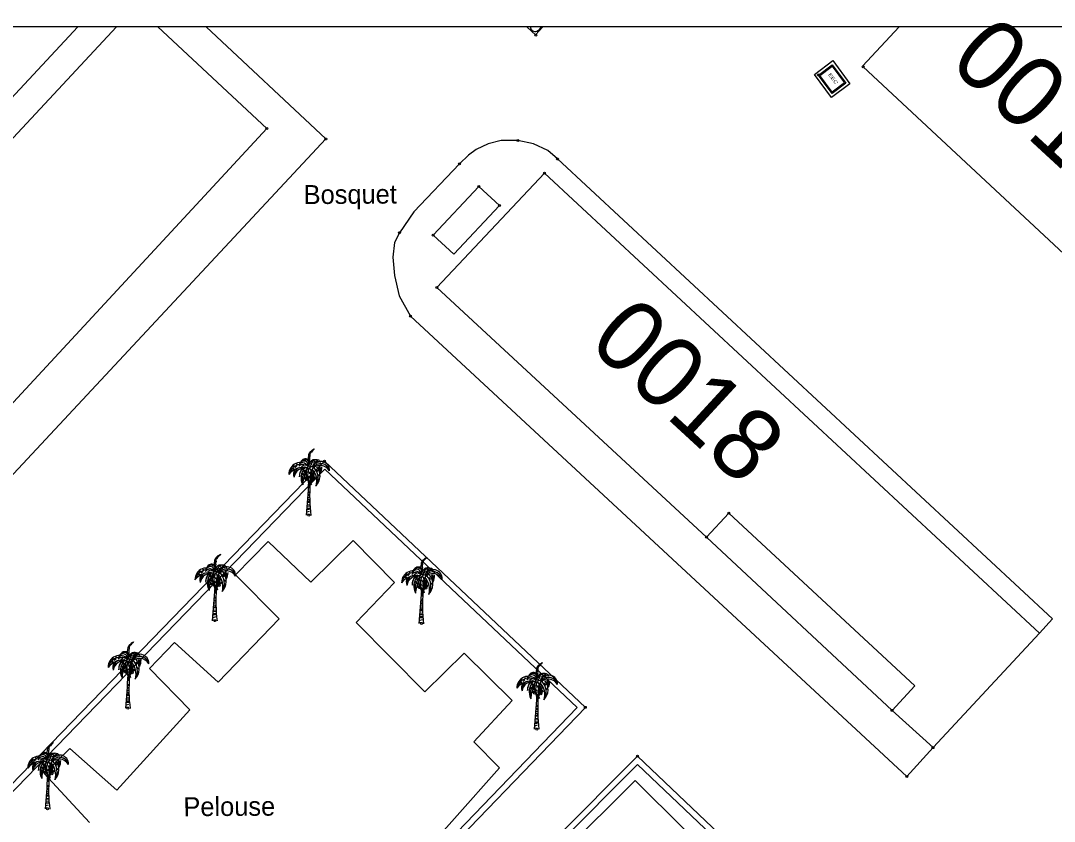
# Model space of a CAD drawing. Extents: x 344013 to 344423, y 298505 to 298795.
# Drawn here: x 344222.4 to 344275.5, y 298751.1 to 298792.2 of the extents above; entities that cross this region are included whole.
import ezdxf

# ---------------------------------------------------------------- set-up
doc = ezdxf.new("R2010")
doc.units = 0
for name, color, linetype in [('Default', 7, 'Continuous'), ('DH_CADRE -CARTOUCHE', 7, 'Continuous'), ('PS_BOLT', 7, 'Continuous'), ('PS_CONST', 7, 'Continuous'), ('PS_DIM', 7, 'Continuous'), ('PS_HIDDEN', 7, 'Continuous'), ('RES_ELECTRICITE', 7, 'Continuous'), ('TOPO_POINT', 7, 'Continuous'), ('VOIRIE_ESPACE VERT', 7, 'Continuous')]:
    doc.layers.add(name, color=color, linetype=linetype)

# ---------------------------------------------------------------- blocks, each defined once
blk = doc.blocks.new('RES_ELECTRICITE')
at = {"layer": 'RES_ELECTRICITE'}
for points in [[(0, 0), (0, 1), (1, 1), (1, 0)], [(0.05, 0.05), (0.05, 0.95), (0.95, 0.95), (0.95, 0.05)]]:
    blk.add_lwpolyline(points, close=True, dxfattribs=at)
blk.add_text('EEC', height=0.2, dxfattribs=at).set_placement((0.237, 0.46))
blk = doc.blocks.new('POINT_DISPLAY')
at = {"layer": 'Default'}
blk.add_circle((0, 0), 0.05, dxfattribs=at)
blk = doc.blocks.new('COCO')
at = {"layer": 'Default'}
for p, q in [((-0.037, 1.06), (0.056, 1.071)), ((0.058, 1.14), (-0.03, 1.162)), ((-0.026, 1.226), (0.061, 1.212)), ((-0.062, 0.537), (0.046, 0.552)), ((0.047, 0.655), (-0.058, 0.642)), ((-0.046, 0.891), (0.052, 0.927)), ((0.054, 0.998), (-0.041, 0.985)), ((0.046, 0.033), (-0.076, 0.051)), ((-0.073, 0.17), (0.045, 0.209)), ((0.045, 0.292), (-0.07, 0.288)), ((-0.068, 0.371), (0.045, 0.374)), ((0.045, 0.47), (-0.065, 0.453))]:
    blk.add_line(p, q, dxfattribs=at)
for points in [[(0.029, 2.551), (-0.016, 2.896), (0.002, 3.125), (0.059, 3.241), (0.173, 3.348), (0.189, 3.356), (0.282, 3.415), (0.266, 3.373), (0.2, 3.318), (0.143, 3.247), (0.093, 3.2), (0.081, 3.165), (0.057, 3.133), (0.057, 3.099), (0.06, 3.037), (0.039, 2.989), (0.039, 2.944), (0.049, 2.877), (0.037, 2.841), (0.013, 2.736)], [(-0.487, 2.68), (-0.386, 2.65)], [(0.013, 2.736), (0.036, 2.813), (0.046, 2.746)], [(0.196, 2.687), (0.323, 2.715)], [(0.283, 2.765), (0.331, 2.786)], [(-0.746, 2.559), (-0.864, 2.483)], [(-0.77, 2.413), (-0.836, 2.333)], [(-0.607, 2.534), (-0.704, 2.443)], [(-0.636, 2.639), (-0.541, 2.608)], [(-0.421, 2.58), (-0.503, 2.523)], [(-0.183, 2.493), (-0.348, 2.417), (-0.401, 2.307), (-0.448, 2.203), (-0.471, 2.086), (-0.474, 2.023), (-0.466, 1.973), (-0.455, 2.054), (-0.451, 2.146), (-0.387, 2.292), (-0.351, 2.354), (-0.284, 2.404), (-0.233, 2.445), (-0.012, 2.495)], [(-0.256, 2.553), (-0.385, 2.508)], [(-0.276, 2.151), (-0.329, 2.086)], [(-0.203, 2.314), (-0.274, 2.258)], [(-0.23, 2.152), (-0.237, 2.043)], [(-0.161, 2.218), (-0.158, 2.122)], [(-0.04, 2.247), (-0.081, 2.179)], [(0.015, 2.414), (-0.056, 2.352)], [(0.022, 2.24), (0.043, 2.13)], [(0.081, 2.404), (0.106, 2.299)], [(0.133, 2.608), (0.185, 2.634)], [(0.385, 2.37), (0.469, 2.254)], [(-0.321, 1.997), (-0.364, 1.9)], [(-0.059, 2.024), (-0.083, 1.998)], [(-0.025, 2.032), (0.002, 1.954)], [(0.473, 2.115), (0.509, 2.012)], [(-0.055, 0.716), (0.048, 0.717), (0.049, 0.787), (-0.051, 0.795)]]:
    blk.add_lwpolyline(points, dxfattribs=at)
for centre, radius in [((-0.187, 1.897), 0.0384), ((-0.144, 1.978), 0.0616), ((-0.124, 1.896), 0.0376), ((-0.11, 1.84), 0.0471), ((0.134, 1.862), 0.0549), ((0.208, 1.822), 0.0626), ((0.254, 1.938), 0.0628)]:
    blk.add_circle(centre, radius, dxfattribs=at)
for centre, radius, start, end in [((-0.427, 2.113), 0.595, 43.6121, 181.4625), ((-0.123, 2.59), 0.323, 122.3475, 158.7636), ((-0.199, 2.618), 0.238, 4.5218, 154.101), ((-0.252, 2.556), 0.231, 4.2441, 134.2103), ((-0.16, 2.647), 0.255, 21.0861, 122.3475), ((0.376, 2.508), 0.372, 113.7681, 175.3309), ((0.376, 2.508), 0.372, 113.7681, 175.3309), ((0.418, 2.527), 0.326, 97.1248, 183.9512), ((1.025, 2.053), 0.958, 126.6858, 153.1664), ((0.618, 2.316), 0.451, 356.1627, 159.0009), ((0.344, 2.407), 0.451, 69.0817, 104.862), ((-1.005, 1.577), 1.786, 37.5668, 40.5156), ((-0.254, 2.28), 0.869, 28.4725, 37.0965), ((0.493, 2.767), 0.0679, 35.3205, 126.6858), ((-0.054, 2.379), 0.738, 25.8194, 35.3205), ((-0.291, 1.543), 0.918, 76.7389, 142.8025), ((-0.38, 1.964), 0.648, 57.9192, 166.6201), ((-0.3, 2.12), 0.482, 151.1331, 199.5942), ((-0.196, 1.874), 0.565, 78.514, 171.3504), ((-0.32, 2.055), 0.433, 119.0834, 188.7621), ((0.362, 1.922), 0.754, 136.7113, 208.8221), ((0.551, 1.79), 0.879, 137.733, 194.3716), ((0.649, 1.599), 0.949, 145.5146, 182.4528), ((0.62, 2.159), 0.753, 153.0868, 230.1124), ((0.659, 2.068), 0.718, 142.3554, 222.2794), ((-0.007, 2.465), 0.0563, 81.7475, 144.3035), ((-0.189, 1.21), 1.324, 71.3715, 81.7475), ((0.294, 2.595), 0.256, 198.6765, 199.7627), ((0.963, 1.939), 0.9, 143.9866, 203.4288), ((0.544, 1.816), 0.474, 137.1953, 172.8987), ((0.308, 2.014), 0.226, 121.4297, 182.29), ((27.302, 0.106), 27.266, 175.4791, 176.5597), ((0.311, 2.152), 0.219, 141.856, 191.5175), ((0.404, 1.878), 0.354, 125.0585, 146.3893), ((0.398, 2.098), 0.301, 136.4569, 162.0685), ((0.357, 2.084), 0.244, 133.1184, 172.7534), ((-0.759, 1.958), 0.922, 344.8505, 15.8988), ((-0.404, 2.045), 0.619, 329.4666, 26.6793), ((-0.289, 2.11), 0.564, 317.8279, 12.3386), ((0.59, 2.015), 0.548, 29.5654, 139.3517), ((-0.543, 1.744), 0.96, 344.8781, 41.1461), ((-0.341, 1.9), 0.828, 46.9767, 50.1231), ((0.609, 2.187), 0.468, 12.1077, 148.3146), ((-0.157, 2.027), 0.74, 51.2475, 54.5217), ((-0.341, 1.9), 0.828, 334.0687, 41.194), ((-0.157, 2.027), 0.74, 315.1472, 39.0239), ((-1.704, 1.849), 2.327, 7.5978, 16.3666), ((-0.254, 2.28), 0.869, 350.8883, 14.7063), ((-0.482, 2.552), 1.161, 339.3597, 356.5925), ((-85.428, 7.294), 85.622, 355.11326, 356.26352), ((-0.279, 1.637), 0.281, 2.1499, 36.6325), ((-0.265, 1.505), 0.316, 339.9997, 25.7228), ((0.199, 1.66), 0.176, 166.9443, 185.5966), ((0.372, 1.847), 0.277, 133.5956, 173.487), ((0.808, 1.542), 0.777, 142.2358, 156.28), ((0.242, 1.964), 0.147, 110.9727, 165.9756)]:
    blk.add_arc(centre, radius, start, end, dxfattribs=at)
blk.add_ellipse((27.425, 0.272), major_axis=(-27.371, 0.966), ratio=0.529859, start_param=6.255729, end_param=6.369141, dxfattribs=at)

msp = doc.modelspace()

# ---------------------------------------------------------------- linework, layer by layer
at = {"layer": 'DH_CADRE -CARTOUCHE'}
msp.add_line((344267.511, 298791.876), (344265.63, 298789.857), dxfattribs=at)
for points in [[(344012.906, 298504.876), (344422.906, 298504.876), (344422.906, 298791.876), (344012.906, 298791.876)], [(344227.296, 298791.876), (344195.443, 298757.689), (344202.327, 298751.376), (344235.016, 298786.657), (344229.42, 298791.876)], [(344257.616, 298765.672), (344258.759, 298766.904), (344268.321, 298758.037), (344267.147, 298756.771), (344269.254, 298754.854), (344274.718, 298760.736), (344249.284, 298784.36), (344243.762, 298778.493)]]:
    msp.add_lwpolyline(points, close=True, dxfattribs=at)
msp.add_lwpolyline([(344265.664, 298789.832), (344278.988, 298777.418), (344285.22, 298784.254), (344277.035, 298791.876)], dxfattribs=at)
at = {"layer": 'PS_BOLT'}
msp.add_line((344238.059, 298786.12), (344231.899, 298791.876), dxfattribs=at)
for points in [[(344225.308, 298791.876), (344193.218, 298757.415), (344202.864, 298748.42), (344238.059, 298786.12)], [(344275.398, 298761.468), (344249.964, 298785.093), (344249.461, 298785.521), (344248.716, 298785.876), (344247.918, 298786.048), (344247.056, 298786.036), (344246.399, 298785.868), (344245.77, 298785.584), (344245.387, 298785.282), (344244.917, 298784.843), (344242.567, 298782.382), (344241.836, 298781.307), (344241.588, 298780.81), (344241.499, 298780.047), (344241.588, 298779.106), (344241.819, 298778.059), (344242.403, 298777.025), (344267.908, 298753.375), (344269.254, 298754.854)], [(344274.718, 298760.736), (344275.398, 298761.468)]]:
    msp.add_lwpolyline(points, dxfattribs=at)
for points in [[(344264.032, 298788.249), (344263.156, 298789.437), (344264.102, 298790.146), (344264.978, 298788.958)], [(344243.572, 298781.173), (344245.915, 298783.682), (344246.98, 298782.709), (344244.636, 298780.199)]]:
    msp.add_lwpolyline(points, close=True, dxfattribs=at)
at = {"layer": 'PS_DIM'}
for p, q in [((344248.409, 298791.876), (344248.399, 298791.864)), ((344248.399, 298791.864), (344248.832, 298791.472)), ((344248.832, 298791.472), (344249.198, 298791.876))]:
    msp.add_line(p, q, dxfattribs=at)
for centre, start_param, end_param in [((344248.856, 298791.934), 2.410238, 3.141492), ((344248.855, 298791.933), 3.141473, 3.926871), ((344248.855, 298791.934), 3.926875, 4.712273), ((344248.856, 298791.933), 4.712292, 5.150907)]:
    msp.add_ellipse(centre, major_axis=(0.211, 0.233), ratio=0.817923, start_param=start_param, end_param=end_param, dxfattribs=at)
at = {"layer": 'PS_HIDDEN'}
msp.add_lwpolyline([(344267.147, 298756.771), (344257.616, 298765.672)], dxfattribs=at)
at = {"layer": 'VOIRIE_ESPACE VERT'}
for points in [[(344228.609, 298733.786), (344215.617, 298746.488), (344237.992, 298769.574), (344251.389, 298756.925), (344242.713, 298747.917), (344242.041, 298748.012), (344241.328, 298747.986), (344240.625, 298747.821), (344240.024, 298747.565), (344239.421, 298747.187), (344239.008, 298746.783), (344238.537, 298746.143), (344238.196, 298745.471), (344238.047, 298744.807), (344237.999, 298744.129), (344238.073, 298743.423)], [(344228.605, 298734.21), (344216.04, 298746.493), (344238.001, 298769.152), (344250.963, 298756.915), (344242.603, 298748.236), (344242.057, 298748.313), (344241.288, 298748.284), (344240.531, 298748.107), (344239.884, 298747.832), (344239.235, 298747.424), (344238.781, 298746.98), (344238.281, 298746.301), (344237.912, 298745.574), (344237.75, 298744.85), (344237.698, 298744.124), (344237.76, 298743.532)], [(344231.266, 298731.391), (344239.817, 298740.14), (344241.041, 298739.766), (344242.189, 298739.766), (344243.184, 298740.005), (344244.081, 298740.424), (344244.633, 298740.88), (344244.997, 298741.263), (344245.477, 298741.91), (344245.824, 298742.729), (344245.996, 298743.636), (344246.014, 298744.465), (344245.874, 298745.265), (344245.627, 298745.935), (344254.062, 298754.412), (344262.797, 298746.113), (344240.559, 298722.574)], [(344231.694, 298731.399), (344239.904, 298739.8), (344240.996, 298739.466), (344242.225, 298739.466), (344243.284, 298739.721), (344244.243, 298740.168), (344244.838, 298740.66), (344245.227, 298741.07), (344245.739, 298741.76), (344246.112, 298742.642), (344246.295, 298743.605), (344246.314, 298744.487), (344246.165, 298745.344), (344245.975, 298745.86), (344254.068, 298753.992), (344262.373, 298746.102), (344240.547, 298722.999)]]:
    msp.add_lwpolyline(points, close=True, dxfattribs=at)
for points in [[(344225.913, 298751.013), (344223.58, 298753.527), (344224.903, 298754.814), (344227.316, 298752.662), (344231.068, 298756.795), (344228.994, 298758.922), (344230.272, 298760.258), (344232.518, 298758.225), (344235.655, 298761.477), (344233.417, 298763.74), (344235.094, 298765.443), (344237.277, 298763.348), (344239.46, 298765.492), (344241.582, 298763.333), (344239.611, 298761.275), (344243.137, 298757.72), (344245.17, 298759.7), (344247.62, 298757.273), (344245.658, 298755.161), (344246.971, 298753.819), (344242.349, 298748.612)], [(344246.524, 298745.78), (344253.955, 298753.169), (344258.996, 298748.148), (344249.672, 298739.461), (344242.635, 298732.378), (344244.519, 298730.394), (344242.565, 298728.46), (344240.743, 298730.084), (344238.616, 298728.105), (344236.471, 298730.146), (344238.473, 298732.251), (344235.868, 298735.019), (344239.835, 298739.286), (344242.288, 298739.15), (344243.975, 298739.62), (344245.332, 298740.713), (344246.081, 298741.85), (344246.468, 298743.19), (344246.662, 298744.121), (344246.579, 298744.964), (344246.524, 298745.78)]]:
    msp.add_lwpolyline(points, dxfattribs=at)

# ---------------------------------------------------------------- block references
at = {"layer": 'RES_ELECTRICITE', "xscale": 1.1766123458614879, "yscale": 0.8822093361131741, "rotation": -53.59149000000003}
msp.add_blockref('RES_ELECTRICITE', (344263.365, 298789.406), dxfattribs=at)
at = {"layer": 'TOPO_POINT'}
for p in [(344248.851, 298791.454), (344263.365, 298789.406), (344265.664, 298789.832), (344235.016, 298786.657), (344238.059, 298786.12), (344247.918, 298786.048), (344244.917, 298784.843), (344249.964, 298785.093), (344249.284, 298784.36), (344245.915, 298783.682), (344246.98, 298782.709), (344241.836, 298781.307), (344243.572, 298781.173), (344243.762, 298778.493), (344242.403, 298777.025), (344237.992, 298769.574), (344237.173, 298766.79), (344258.759, 298766.904), (344257.616, 298765.672), (344232.352, 298761.377), (344242.968, 298761.23), (344227.886, 298756.882), (344251.389, 298756.925), (344267.147, 298756.771), (344248.89, 298755.811), (344269.254, 298754.854), (344254.062, 298754.412), (344267.908, 298753.375), (344223.758, 298751.706)]:
    msp.add_blockref('POINT_DISPLAY', p, dxfattribs=at)
at = {"layer": 'VOIRIE_ESPACE VERT'}
for p in [(344237.173, 298766.79), (344232.352, 298761.377), (344242.968, 298761.23), (344227.886, 298756.882), (344248.89, 298755.811), (344223.758, 298751.706)]:
    msp.add_blockref('COCO', p, dxfattribs=at)

# ---------------------------------------------------------------- texts
at = {"layer": 'PS_CONST'}
for s, height, rotation, p in [('0019', 3.662, 317.327, (344269.976, 298789.978)), ('Bosquet', 0.9758, 0.3665, (344236.916, 298782.775)), ('0018', 3.662, 317.3839, (344251.446, 298775.565)), ('Pelouse', 0.9758, 0.3665, (344230.738, 298751.332))]:
    msp.add_text(s, height=height, rotation=rotation, dxfattribs=at).set_placement(p)

doc.saveas('drawing.dxf')
